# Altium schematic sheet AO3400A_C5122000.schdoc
size 127 x 101 mm
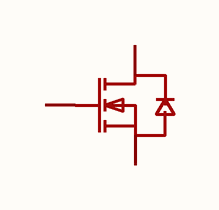
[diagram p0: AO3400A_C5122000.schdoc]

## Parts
Q?  ao3400a_c5122000  [SOT-23-3_L2.9-W1.3-P1.90-LS2.4-BR]  (value not drawn)

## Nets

Not connected (* = marked no-connect by the designer): Q? 1(G) 2(S) 3(D)

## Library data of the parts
Q? = ao3400a_c5122000: 数量:1个N沟道;漏源电压(Vdss):30V;连续漏极电流(Id):5.8A;导通电阻(RDS(on)):59mΩ@2.5V;耗散功率(Pd):1.4W;阈值电压(Vgs(th)):1.4V;; Manufacturer: TECH PUBLIC(台舟); AddInBom: yes; ModelId: c62791f0466c4ae2a892c056b845b0ca; ModelName: SOT-23-3P_L2.9-W1.3-H1.0-LS2.4-P0.95; ModelTransform: 98.425,114.173,0,180,0,0,0.0005,-0.0005,0; Number: 1个N沟道; Drain to Source Voltage: 30V; Current - Continuous Drain(Id): 5.8A; Pd - Power Dissipation: 1.4W; Gate Threshold Voltage (Vgs(th)): 1.4V; Gate Charge(Qg): 9.5nC@15V; Input Capacitance(Ciss): 820pF; Reverse Transfer Capacitance (Crss@Vds): 77pF; Type: N沟道; Output Capacitance(Coss): 99pF; Vgs: ±12V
